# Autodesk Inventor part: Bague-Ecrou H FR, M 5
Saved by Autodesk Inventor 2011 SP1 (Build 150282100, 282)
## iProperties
Created: 2010-12
Part Number: Bague-Ecrou H FR, M 5
Document SubType Name: Modeling
Designer: eric
Density: 1 g/cm^3
Mass: 0.0222516 g
Surface Area: 0.738747 cm^2
Volume: 0.0222516 cm^3
Author: eric
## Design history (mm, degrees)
feature "Base1"
node "Solide1"
node "Corps solides"
node "Corps surfaciques"
